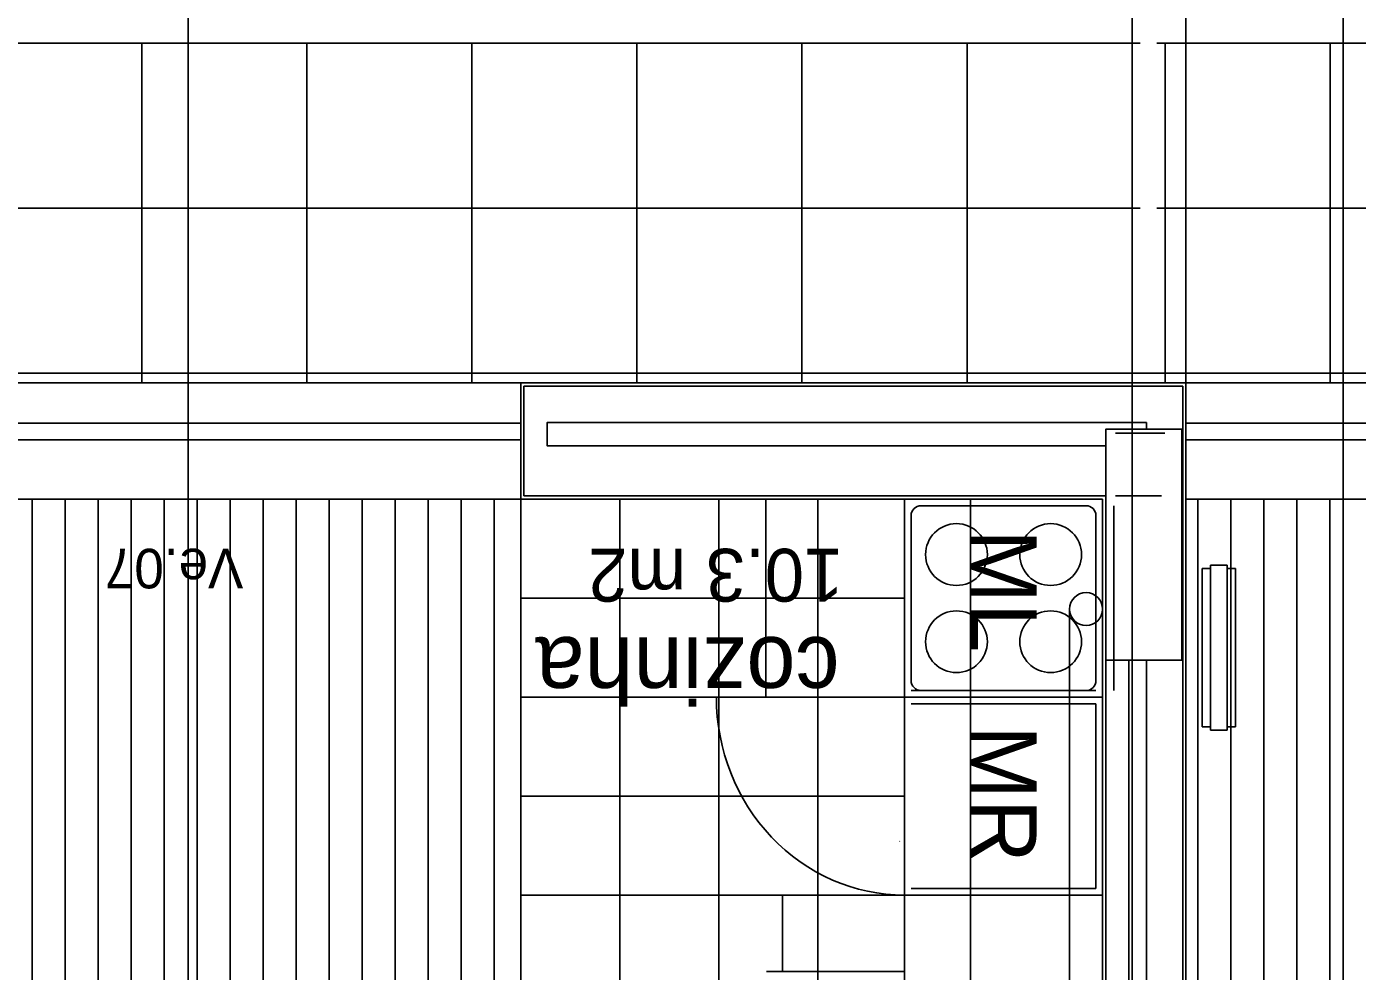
# Model space of a CAD drawing. Extents: x 1248 to 1356, y -443 to -224.
# Drawn here: x 1308.119 to 1312.151, y -233.707 to -230.844 of the extents above; entities that cross this region are included whole.
import ezdxf

# ---------------------------------------------------------------- set-up
doc = ezdxf.new("R2010")
doc.units = 0
for name, color, linetype in [('corte', 7, 'Continuous'), ('estereoctomias', 7, 'Continuous'), ('Level 1', 7, 'Continuous'), ('Level 10', 7, 'Continuous'), ('Level 11', 7, 'Continuous'), ('Level 13', 7, 'Continuous'), ('Level 2', 7, 'Continuous'), ('Level 21', 7, 'Continuous'), ('Level 3', 7, 'Continuous'), ('Level 4', 7, 'Continuous'), ('Level 40', 7, 'Continuous'), ('Level 59', 7, 'Continuous'), ('Level 60', 7, 'Continuous'), ('mob-fixo', 7, 'Continuous'), ('revestimentos', 7, 'Continuous'), ('vermelhos-cont', 7, 'Continuous'), ('vermelhos-tracej', 7, 'Continuous')]:
    doc.layers.add(name, color=color, linetype=linetype)

msp = doc.modelspace()

# ---------------------------------------------------------------- linework, layer by layer
at = {"layer": 'corte'}
for p, q in [((1311.6219, -231.934), (1309.6262, -231.934)), ((1311.6219, -235.1452), (1311.6219, -231.934)), ((1311.6219, -234.8352), (1311.6219, -231.934)), ((1311.5119, -232.0639), (1311.5119, -232.044)), ((1311.389, -232.2659), (1311.389, -235.0752)), ((1311.6812, -232.4859), (1311.6812, -232.9659)), ((1311.7062, -232.4859), (1311.6812, -232.4859)), ((1311.7062, -232.4759), (1311.7062, -232.9759)), ((1311.7562, -232.4759), (1311.7062, -232.4759)), ((1311.7562, -232.4759), (1311.7562, -232.9759)), ((1311.7812, -232.4859), (1311.7562, -232.4859)), ((1311.7812, -232.9659), (1311.7812, -232.4859)), ((1311.459, -232.7639), (1311.459, -236.1213)), ((1311.5119, -236.1213), (1311.5119, -232.7639)), ((1311.7062, -232.9659), (1311.6812, -232.9659)), ((1311.7562, -232.9759), (1311.7062, -232.9759)), ((1311.7812, -232.9659), (1311.7562, -232.9659))]:
    msp.add_line(p, q, dxfattribs=at)
msp.add_lwpolyline([(1311.389, -232.7639), (1311.619, -232.7639), (1311.619, -232.0639), (1311.389, -232.0639)], close=True, dxfattribs=at)
at = {"layer": 'estereoctomias'}
for points in [[(1311.6219, -231.934), (1309.6262, -231.934), (1309.6262, -232.2659), (1311.389, -232.2659), (1311.389, -232.1143), (1309.6962, -232.1143), (1309.6962, -232.044), (1311.5119, -232.044), (1311.5119, -232.0639), (1311.6219, -232.0639)], [(1311.459, -232.7639), (1311.459, -236.1213), (1311.389, -236.1213), (1311.389, -235.1452), (1309.3528, -235.1452), (1309.3528, -235.0752), (1311.389, -235.0752), (1311.389, -232.7639)], [(1311.5119, -232.7639), (1311.6219, -232.7639), (1311.6219, -235.0752), (1311.6214, -235.073), (1311.6219, -235.1452), (1311.6219, -235.1452), (1311.6219, -236.1213), (1311.5119, -236.1213)], [(1311.5119, -232.7639), (1311.6219, -232.7639), (1311.6219, -234.8352), (1312.0319, -234.8352), (1312.0319, -234.9052), (1311.6219, -234.9052), (1311.6219, -236.1213), (1311.5119, -236.1213)]]:
    msp.add_lwpolyline(points, close=True, dxfattribs=at)
at = {"layer": 'Level 1'}
for p, q in [((1309.6262, -232.2659), (1309.6262, -231.934)), ((1309.6962, -232.044), (1311.5119, -232.044)), ((1309.6962, -232.1143), (1309.6962, -232.044)), ((1311.4177, -232.0759), (1311.5677, -232.0759)), ((1311.389, -232.1143), (1309.6962, -232.1143)), ((1311.389, -232.2659), (1309.6262, -232.2659)), ((1311.4177, -232.2659), (1311.5577, -232.2659))]:
    msp.add_line(p, q, dxfattribs=at)
at = {"layer": 'Level 10'}
for p, q in [((1307.4433, -230.894), (1311.4933, -230.894)), ((1308.4683, -230.894), (1308.4683, -231.924)), ((1308.9683, -230.894), (1308.9683, -231.924)), ((1309.4683, -230.894), (1309.4683, -231.924)), ((1309.9683, -230.894), (1309.9683, -231.924)), ((1310.4683, -230.894), (1310.4683, -231.924)), ((1310.9683, -230.894), (1310.9683, -231.924)), ((1311.4683, -230.894), (1311.4683, -231.924)), ((1311.5433, -230.894), (1315.5933, -230.894)), ((1311.5683, -230.894), (1311.5683, -231.924)), ((1312.0683, -230.894), (1312.0683, -231.924)), ((1307.4433, -231.394), (1311.4933, -231.394)), ((1311.5433, -231.394), (1315.5933, -231.394)), ((1307.4683, -231.894), (1311.4933, -231.894)), ((1311.4933, -231.894), (1315.5933, -231.894)), ((1308.1362, -232.2759), (1308.1362, -236.9259)), ((1308.2362, -232.2759), (1308.2362, -236.9259)), ((1308.3362, -232.2759), (1308.3362, -236.9259)), ((1308.4362, -232.2759), (1308.4362, -236.9259)), ((1308.5362, -232.2759), (1308.5362, -236.9259)), ((1308.6362, -232.2759), (1308.6362, -236.9259)), ((1308.7362, -232.2759), (1308.7362, -236.9259)), ((1308.8362, -232.2759), (1308.8362, -236.9259)), ((1308.9362, -232.2759), (1308.9362, -236.9109)), ((1309.0362, -232.2759), (1309.0362, -236.9259)), ((1309.1362, -232.2759), (1309.1362, -236.9259)), ((1309.2362, -232.2759), (1309.2362, -236.9259)), ((1309.3362, -232.2759), (1309.3362, -234.4652)), ((1309.4362, -232.2759), (1309.4362, -234.4652)), ((1309.5362, -232.2759), (1309.5362, -234.4652)), ((1309.6162, -232.2759), (1309.6162, -234.4652)), ((1309.9162, -232.2759), (1309.9162, -234.4652)), ((1310.2162, -232.2759), (1310.2162, -234.4652)), ((1310.5162, -232.2759), (1310.5162, -234.4652)), ((1311.6677, -232.2759), (1311.6677, -234.8252)), ((1311.7677, -232.2759), (1311.7677, -234.8252)), ((1311.8677, -232.2759), (1311.8677, -234.8252)), ((1311.9677, -232.2759), (1311.9677, -234.8252)), ((1312.0677, -232.2759), (1312.0677, -236.9109))]:
    msp.add_line(p, q, dxfattribs=at)
at = {"layer": 'Level 13'}
for p, q in [((1310.799, -232.826), (1310.799, -232.326)), ((1310.829, -232.296), (1311.329, -232.296)), ((1311.359, -232.826), (1311.359, -232.326)), ((1310.829, -232.856), (1311.329, -232.856))]:
    msp.add_line(p, q, dxfattribs=at)
for centre in [(1310.9364, -232.4439), (1311.2216, -232.4439), (1310.9364, -232.7081), (1311.2216, -232.7081)]:
    msp.add_circle(centre, 0.0936, dxfattribs=at)
for centre, start, end in [((1310.829, -232.326), 90.0001, 180), ((1311.329, -232.326), 0.0002, 90), ((1310.829, -232.826), 180.0001, 270.0001), ((1311.329, -232.826), 269.9999, 0.0002)]:
    msp.add_arc(centre, 0.03, start, end, dxfattribs=at)
at = {"layer": 'Level 2'}
for p, q in [((1307.5975, -231.924), (1309.6162, -231.924)), ((1311.6312, -231.924), (1313.6462, -231.924)), ((1307.5975, -232.0459), (1309.6162, -232.0459)), ((1311.6312, -232.0459), (1313.6462, -232.0459)), ((1307.5975, -232.0959), (1309.6162, -232.0959)), ((1311.6312, -232.0959), (1313.6462, -232.0959)), ((1307.5975, -232.2759), (1309.6162, -232.2759)), ((1310.779, -232.2759), (1310.779, -234.4652)), ((1311.6312, -232.2759), (1313.6462, -232.2759))]:
    msp.add_line(p, q, dxfattribs=at)
at = {"layer": 'Level 21'}
for p, q in [((1309.6162, -232.5759), (1310.779, -232.5759)), ((1309.6162, -232.8759), (1310.779, -232.8759)), ((1309.6162, -233.1759), (1310.779, -233.1759)), ((1309.6162, -233.4759), (1310.779, -233.4759))]:
    msp.add_line(p, q, dxfattribs=at)
at = {"layer": 'Level 3'}
msp.add_line((1310.979, -232.2759), (1310.979, -234.4652), dxfattribs=at)
msp.add_arc((1310.7655, -233.7556), 0.4426, 89.99999999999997, 90.00000277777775, dxfattribs=at)
at = {"layer": 'Level 4'}
for p, q in [((1310.359, -232.8759), (1310.359, -232.2759)), ((1311.4129, -232.8559), (1311.4129, -232.2959)), ((1311.359, -232.8559), (1310.799, -232.8559)), ((1310.7662, -232.8759), (1310.1662, -232.8759)), ((1311.379, -232.8759), (1310.779, -232.8759)), ((1310.799, -232.8959), (1311.359, -232.8959)), ((1311.359, -233.4559), (1311.359, -232.8959)), ((1310.799, -233.4559), (1311.359, -233.4559)), ((1310.7662, -233.4759), (1310.3662, -233.4759)), ((1310.409, -233.4759), (1310.409, -233.7072)), ((1310.779, -233.4759), (1311.379, -233.4759)), ((1310.779, -233.7072), (1310.361, -233.7072))]:
    msp.add_line(p, q, dxfattribs=at)
msp.add_ellipse((1310.779, -232.8759), major_axis=(0, 0.6), ratio=0.95, start_param=1.570796, end_param=3.141593, dxfattribs=at)
at = {"layer": 'Level 59'}
msp.add_lwpolyline([(1312.108, -245.3846), (1306.9649, -245.3846), (1306.9649, -230.4331), (1312.108, -230.4331)], close=True, dxfattribs=at)
at = {"layer": 'mob-fixo'}
msp.add_line((1311.279, -232.609), (1311.279, -235.0402), dxfattribs=at)
msp.add_circle((1311.329, -232.609), 0.05, dxfattribs=at)
at = {"layer": 'revestimentos'}
for p, q in [((1311.6312, -231.924), (1309.6162, -231.924)), ((1309.6162, -232.2759), (1309.6162, -231.924)), ((1311.6312, -234.8252), (1311.6312, -231.924)), ((1311.6312, -234.8252), (1311.6312, -231.924)), ((1311.379, -232.2759), (1309.6162, -232.2759)), ((1311.379, -232.2759), (1311.379, -235.0652))]:
    msp.add_line(p, q, dxfattribs=at)
at = {"layer": 'vermelhos-cont'}
msp.add_line((1311.469, -250.7923), (1311.469, -229.6198), dxfattribs=at)
at = {"layer": 'vermelhos-tracej'}
for p, q in [((1308.6087, -235.3039), (1308.6087, -224.3117)), ((1311.6312, -235.3039), (1311.6312, -224.3117))]:
    msp.add_line(p, q, dxfattribs=at)

# ---------------------------------------------------------------- texts
at = {"layer": 'Level 11'}
for s, p in [('ML', (1310.979, -232.3681)), ('MR', (1310.979, -232.9621))]:
    msp.add_text(s, height=0.2, rotation=270, dxfattribs=at).set_placement(p)
at = {"layer": 'Level 40'}
msp.add_text('Ve.07', height=0.12, rotation=180, dxfattribs=at).set_placement((1308.7758, -232.4264))
at = {"layer": 'Level 60'}
for s, height, p in [('10.3 m2', 0.16, (1310.5936, -232.4265)), ('cozinha', 0.2, (1310.5825, -232.6943))]:
    msp.add_text(s, height=height, rotation=180, dxfattribs=at).set_placement(p)

doc.saveas('drawing.dxf')
